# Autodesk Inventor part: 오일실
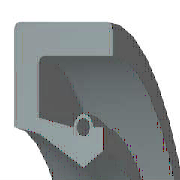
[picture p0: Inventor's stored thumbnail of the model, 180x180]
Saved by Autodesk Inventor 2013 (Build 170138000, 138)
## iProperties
Created: 2009-02
Part Number: 오일실
Material: 고무
Description: 오일-실
Document SubType Name: Modeling
Standard: KS B 2804
Designer: KYOUNG IL JANG
Standards Organization: KS
Language: ko-KR
Size Designation: S - 18 30 8
Categories: <MemberInstance><Categories><Category DisplayName="샤프트 부품" InternalName="7f7aeb1f-a693-4053-b835-cee3144e0d98" Mnemonic="SHFT"><Category DisplayName="실링" Intern
Density: 0.93 g/cm^3
Company: 한국ATC센터
IsCustomPart: 1
Author: KYOUNG IL JANG
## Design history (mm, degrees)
revolve "본체" stored, may be unused: angle "d17" = 90 deg
revolve "스프링1" stored, may be unused: angle "d18" = 90 deg
body "Solid1"
sketch "스케치1"
  geometry: L1 (0, 15)-(8, 15); L2 (8, 15)-(8, 13.75); L3 (8, 13.75)-(1.75, 13.75); L4 (0, 15)-(0, 11.1); L5 (0, 11.1)-(1.75, 10.75); L6 (1.75, 10.75)-(4.9, 9); L7 (4.9, 9)-(0, 9); L8 (6.3, 9.875)-(6.3, 11.1); L9 (0, 0)-(9.586, 0) reference; L10 (4.9, 9)-(6.3, 9.875); L11 (0, 18)-(0, -3) reference; L12 (-1.917, 0)-(11.503, 0) reference; L13 (4.2, 11.1)-(1.75, 11.59); L14 (1.75, 11.59)-(1.75, 13.75); L15 (6.3, 11.1)-(5.6, 11.1); C1 r 0.455 at (4.9, 11.1); A1 r 0.7 centre (4.9, 11.1) between (5.6, 11.1) and (4.2, 11.1)
  constraints: 26 end point, 5 horizontal alignment, 4 perpendicular, 2 centre point, 2 collinear, 2 horizontal, 2 parallel, 2 point on circle, 2 point on line, 2 vertical alignment, 1 coincident
  dimensions: "d0" = 30 diameter of L1 L9 (= SD2); "d1" = 19.75 diameter of L8.start L9 (= ABDM); "d2" = 1.25 distance of L1.end L2.end (computed from SD); "d3" = 0.91 diameter of C1 (= SPDI); "d4" = 1.4 diameter of A1 (= SPDA); "d5" = 18 diameter of L6.end L9 (= NND); "d6" = 21.5 diameter of L5.end L9 (= TKDM); "d7" = 22.2 diameter of L4.end L9 (= HLDM); "d8" = 4.9 distance from line of C1.centre L4 (= SPDST); "d9" = 6.3 distance between parallel lines of L8 L4 (= SDI); "d10" = 8 distance between parallel lines of L2 L4 (= SWDT); "d12" = 1.75 distance between parallel lines of L14 L4 (= SD)
fillet "모깎기1" dims "d11" = 0.3 (= RR)
other parameters: "SD2" = 30 [user parameter; used in 1 equation term], "SWDT" = 8 [user parameter; used in 1 equation term], "RR" = 0.3 [user parameter; used in 1 equation term], "SD" = 1.75 [user parameter; used in 2 equation terms], "NND" = 18 [user parameter; used in 1 equation term], "SPDA" = 1.4 [user parameter; used in 1 equation term], "SPDI" = 0.91 [user parameter; used in 1 equation term], "TKDM" = 21.5 [user parameter; used in 1 equation term], "HLDM" = 22.2 [user parameter; used in 1 equation term], "ABDM" = 19.75 [user parameter; used in 1 equation term], "SDI" = 6.3 [user parameter; used in 1 equation term], "SPDST" = 4.9 [user parameter; used in 1 equation term], "d13" = 0, "d14" = 0, "d15" = 0, "LAB" = 0.35 [user parameter]
